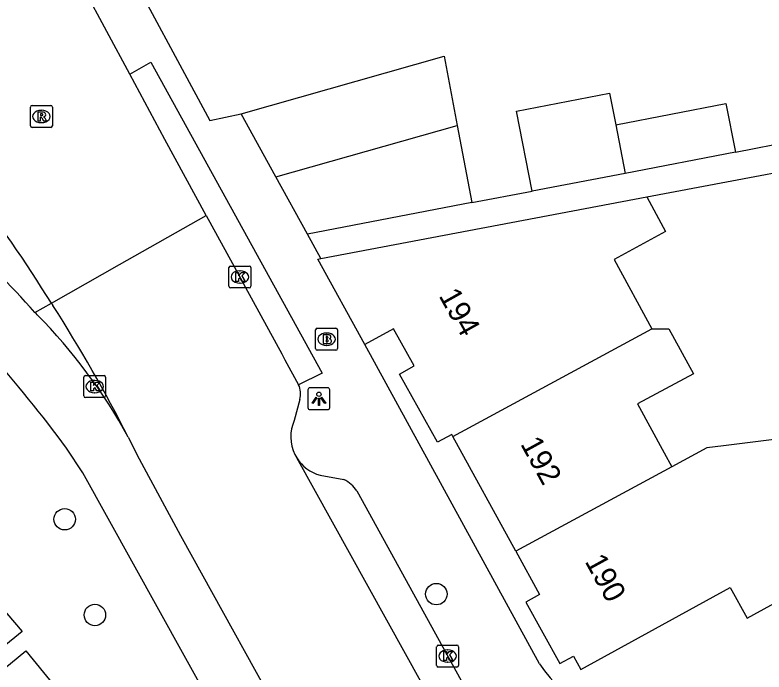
# Model space of a CAD drawing. Extents: x 159053 to 160041, y 380450 to 381422.
# Drawn here: x 159235.06 to 159269.24, y 381203.53 to 381233.5 of the extents above; entities that cross this region are included whole.
import ezdxf

# ---------------------------------------------------------------- set-up
doc = ezdxf.new("R2010")
doc.units = 0
for name, color, linetype in [('IMGEO_Boom', 7, 'Continuous'), ('IMGEO_Brandkraan', 7, 'Continuous'), ('IMGEO_Fietspad_gesloten', 7, 'Continuous'), ('IMGEO_Kolk', 7, 'Continuous'), ('IMGEO_Lage_trafo', 7, 'Continuous'), ('IMGEO_Lichtpunt', 7, 'Continuous'), ('IMGEO_Muur', 7, 'Continuous'), ('IMGEO_Pand', 7, 'Continuous'), ('IMGEO_Pand_nummerreeks', 7, 'Continuous'), ('IMGEO_Parkeervlak_open', 7, 'Continuous'), ('IMGEO_Rijbaan_lokaal_gesloten', 7, 'Continuous'), ('IMGEO_Rioolput', 7, 'Continuous'), ('IMGEO_Voetpad_open', 7, 'Continuous')]:
    doc.layers.add(name, color=color, linetype=linetype)

msp = doc.modelspace()

# ---------------------------------------------------------------- linework, layer by layer
at = {"layer": 'IMGEO_Boom'}
for centre in [(159237.327, 381210.495), (159254.284, 381207.078), (159238.704, 381206.128)]:
    msp.add_circle(centre, 0.489, dxfattribs=at)
at = {"layer": 'IMGEO_Brandkraan'}
for p, q in [((159248.777, 381218.282), (159248.777, 381219.134)), ((159248.852, 381219.208), (159249.704, 381219.208)), ((159249.265, 381218.988), (159249.29, 381218.988)), ((159249.778, 381219.134), (159249.778, 381218.282)), ((159249.288, 381218.428), (159249.263, 381218.428)), ((159249.704, 381218.208), (159248.852, 381218.208))]:
    msp.add_line(p, q, dxfattribs=at)
for points in [[(159248.777, 381218.282), (159248.777, 381219.134)], [(159248.852, 381219.208), (159249.704, 381219.208)], [(159249.778, 381219.134), (159249.778, 381218.282)], [(159249.125, 381218.908), (159249.125, 381218.508), (159249.338, 381218.508)], [(159249.356, 381218.908), (159249.125, 381218.908)], [(159249.304, 381218.827), (159249.25, 381218.827), (159249.25, 381218.751)], [(159249.25, 381218.751), (159249.303, 381218.751)], [(159249.312, 381218.675), (159249.25, 381218.675), (159249.25, 381218.594)], [(159249.25, 381218.594), (159249.312, 381218.594)], [(159249.704, 381218.208), (159248.852, 381218.208)]]:
    msp.add_lwpolyline(points, dxfattribs=at)
for centre, radius, start, end in [((159248.854, 381219.132), 0.0765, 91.552, 178.448), ((159248.854, 381219.132), 0.0765, 91.552, 178.448), ((159249.702, 381219.132), 0.0765, 1.552, 88.448), ((159249.702, 381219.132), 0.0765, 1.552, 88.448), ((159249.305, 381218.789), 0.0379, 267.8285, 90.9355), ((159249.313, 381218.634), 0.0404, 269.8759, 90.5077), ((159249.36, 381218.763), 0.145, 59.4692, 91.5367), ((159249.385, 381218.81), 0.0922, 285.5137, 58.1501), ((159249.39, 381218.618), 0.105, 301.3115, 78.989), ((159248.854, 381218.284), 0.0765, 181.552, 268.448), ((159248.854, 381218.284), 0.0765, 181.552, 268.448), ((159249.344, 381218.759), 0.251, 268.6676, 293.5347), ((159249.702, 381218.284), 0.0765, 271.552, 358.448), ((159249.702, 381218.284), 0.0765, 271.552, 358.448)]:
    msp.add_arc(centre, radius, start, end, dxfattribs=at)
for centre, major_axis, ratio, start_param, end_param in [((159249.264, 381218.708), (-0.387, 0.002), 0.722429, 4.712389, 7.853982), ((159249.289, 381218.708), (-0.39, 0.002), 0.717154, 1.570796, 4.712389)]:
    msp.add_ellipse(centre, major_axis=major_axis, ratio=ratio, start_param=start_param, end_param=end_param, dxfattribs=at)
at = {"layer": 'IMGEO_Fietspad_gesloten'}
for points in [[(159235.971, 381219.934), (159236.718, 381220.356)], [(159236.071, 381219.823), (159236.021, 381219.878), (159235.971, 381219.934)]]:
    msp.add_lwpolyline(points, dxfattribs=at)
for centre, radius, start, end in [((159194.705, 381182.561), 55.674, 42.1662, 52.6419), ((159218.247, 381202.22), 25.051, 28.6786, 44.6428)]:
    msp.add_arc(centre, radius, start, end, dxfattribs=at)
at = {"layer": 'IMGEO_Kolk'}
for p, q in [((159244.895, 381222.047), (159245.747, 381222.047)), ((159244.82, 381221.121), (159244.82, 381221.973)), ((159245.308, 381221.827), (159245.333, 381221.827)), ((159245.821, 381221.973), (159245.821, 381221.121)), ((159245.747, 381221.047), (159244.895, 381221.047)), ((159245.331, 381221.267), (159245.306, 381221.267)), ((159238.194, 381216.121), (159238.194, 381216.973)), ((159238.269, 381217.047), (159239.121, 381217.047)), ((159239.195, 381216.973), (159239.195, 381216.121)), ((159238.682, 381216.827), (159238.707, 381216.827)), ((159238.705, 381216.267), (159238.68, 381216.267)), ((159239.121, 381216.047), (159238.269, 381216.047)), ((159254.299, 381203.828), (159254.299, 381204.68)), ((159254.374, 381204.754), (159255.226, 381204.754)), ((159255.3, 381204.68), (159255.3, 381203.828)), ((159254.787, 381204.534), (159254.812, 381204.534)), ((159254.81, 381203.974), (159254.785, 381203.974)), ((159255.226, 381203.754), (159254.374, 381203.754))]:
    msp.add_line(p, q, dxfattribs=at)
for points in [[(159244.895, 381222.047), (159245.747, 381222.047)], [(159244.82, 381221.121), (159244.82, 381221.973)], [(159245.141, 381221.747), (159245.264, 381221.747), (159245.264, 381221.596), (159245.394, 381221.747), (159245.558, 381221.747), (159245.412, 381221.596), (159245.565, 381221.347), (159245.413, 381221.347), (159245.328, 381221.511), (159245.264, 381221.444), (159245.264, 381221.347), (159245.141, 381221.347), (159245.141, 381221.747)], [(159245.821, 381221.973), (159245.821, 381221.121)], [(159245.747, 381221.047), (159244.895, 381221.047)], [(159238.194, 381216.121), (159238.194, 381216.973)], [(159238.269, 381217.047), (159239.121, 381217.047)], [(159239.195, 381216.973), (159239.195, 381216.121)], [(159238.515, 381216.747), (159238.638, 381216.747), (159238.638, 381216.596), (159238.768, 381216.747), (159238.932, 381216.747), (159238.786, 381216.596), (159238.939, 381216.347), (159238.787, 381216.347), (159238.702, 381216.511), (159238.638, 381216.444), (159238.638, 381216.347), (159238.515, 381216.347), (159238.515, 381216.747)], [(159239.121, 381216.047), (159238.269, 381216.047)], [(159254.299, 381203.828), (159254.299, 381204.68)], [(159254.374, 381204.754), (159255.226, 381204.754)], [(159255.3, 381204.68), (159255.3, 381203.828)], [(159254.62, 381204.454), (159254.743, 381204.454), (159254.743, 381204.303), (159254.873, 381204.454), (159255.037, 381204.454), (159254.891, 381204.303), (159255.044, 381204.054), (159254.892, 381204.054), (159254.807, 381204.218), (159254.743, 381204.151), (159254.743, 381204.054), (159254.62, 381204.054), (159254.62, 381204.454)], [(159255.226, 381203.754), (159254.374, 381203.754)]]:
    msp.add_lwpolyline(points, dxfattribs=at)
for centre, start, end in [((159244.897, 381221.971), 91.552, 178.448), ((159244.897, 381221.971), 91.552, 178.448), ((159245.745, 381221.971), 1.552, 88.448), ((159245.745, 381221.971), 1.552, 88.448), ((159244.897, 381221.123), 181.552, 268.448), ((159244.897, 381221.123), 181.552, 268.448), ((159245.745, 381221.123), 271.552, 358.448), ((159245.745, 381221.123), 271.552, 358.448), ((159238.271, 381216.971), 91.552, 178.448), ((159238.271, 381216.971), 91.552, 178.448), ((159239.119, 381216.971), 1.552, 88.448), ((159239.119, 381216.971), 1.552, 88.448), ((159238.271, 381216.123), 181.552, 268.448), ((159238.271, 381216.123), 181.552, 268.448), ((159239.119, 381216.123), 271.552, 358.448), ((159239.119, 381216.123), 271.552, 358.448), ((159254.376, 381204.678), 91.552, 178.448), ((159254.376, 381204.678), 91.552, 178.448), ((159255.224, 381204.678), 1.552, 88.448), ((159255.224, 381204.678), 1.552, 88.448), ((159254.376, 381203.83), 181.552, 268.448), ((159254.376, 381203.83), 181.552, 268.448), ((159255.224, 381203.83), 271.552, 358.448), ((159255.224, 381203.83), 271.552, 358.448)]:
    msp.add_arc(centre, 0.0765, start, end, dxfattribs=at)
for centre, major_axis, ratio, start_param, end_param in [((159245.307, 381221.547), (-0.387, 0.002), 0.722429, 4.712389, 7.853982), ((159245.332, 381221.547), (-0.39, 0.002), 0.717154, 1.570796, 4.712389), ((159238.681, 381216.547), (-0.387, 0.002), 0.722429, 4.712389, 7.853982), ((159238.706, 381216.547), (-0.39, 0.002), 0.717154, 1.570796, 4.712389), ((159254.786, 381204.254), (-0.387, 0.002), 0.722429, 4.712389, 7.853982), ((159254.811, 381204.254), (-0.39, 0.002), 0.717154, 1.570796, 4.712389)]:
    msp.add_ellipse(centre, major_axis=major_axis, ratio=ratio, start_param=start_param, end_param=end_param, dxfattribs=at)
at = {"layer": 'IMGEO_Lage_trafo'}
msp.add_lwpolyline([(159234.224, 381203.411), (159235.554, 381204.496), (159236.832, 381202.93), (159235.531, 381201.869)], dxfattribs=at)
at = {"layer": 'IMGEO_Lichtpunt'}
for p, q in [((159248.426, 381216.396), (159248.426, 381215.589)), ((159248.426, 381216.396), (159248.426, 381215.589)), ((159249.328, 381216.491), (159248.52, 381216.491)), ((159249.328, 381216.491), (159248.52, 381216.491)), ((159249.422, 381215.589), (159249.422, 381216.396)), ((159249.422, 381215.589), (159249.422, 381216.396)), ((159248.52, 381215.495), (159249.328, 381215.495)), ((159248.52, 381215.495), (159249.328, 381215.495))]:
    msp.add_line(p, q, dxfattribs=at)
for points in [[(159248.8, 381216.06), (159248.839, 381216.032), (159248.651, 381215.77), (159248.613, 381215.797), (159248.8, 381216.06)], [(159248.902, 381216.012), (159248.949, 381216.012), (159248.949, 381215.69), (159248.902, 381215.69), (159248.902, 381216.012)], [(159249.012, 381216.032), (159249.05, 381216.059), (159249.237, 381215.797), (159249.198, 381215.769), (159249.012, 381216.032)]]:
    msp.add_lwpolyline(points, dxfattribs=at)
msp.add_circle((159248.925, 381216.194), 0.0994, dxfattribs=at)
for centre, start, end in [((159248.52, 381216.396), 90, 180), ((159248.52, 381216.396), 90, 180), ((159249.328, 381216.396), 0, 90), ((159249.328, 381216.396), 0, 90), ((159248.52, 381215.589), 180, 270), ((159248.52, 381215.589), 180, 270), ((159249.328, 381215.589), 270, 0), ((159249.328, 381215.589), 270, 360)]:
    msp.add_arc(centre, 0.0946, start, end, dxfattribs=at)
at = {"layer": 'IMGEO_Muur'}
msp.add_lwpolyline([(159237.275, 381243.932), (159239.731, 381236.517), (159243.948, 381228.686), (159245.372, 381228.997)], dxfattribs=at)
at = {"layer": 'IMGEO_Pand'}
for points in [[(159245.372, 381228.997), (159254.638, 381231.622), (159255.241, 381228.458)], [(159258.651, 381225.462), (159257.941, 381229.115), (159262.185, 381229.94), (159262.468, 381228.486)], [(159262.468, 381228.486), (159267.497, 381229.462), (159267.929, 381227.242)], [(159246.963, 381226.113), (159245.372, 381228.997)], [(159246.963, 381226.113), (159255.241, 381228.458)], [(159255.241, 381228.458), (159255.91, 381224.943)], [(159262.468, 381228.486), (159262.901, 381226.266)], [(159267.929, 381227.242), (159262.901, 381226.266)], [(159248.408, 381223.494), (159246.963, 381226.113)], [(159262.901, 381226.266), (159258.651, 381225.462)], [(159249.008, 381222.383), (159263.884, 381225.197)], [(159263.884, 381225.197), (159264.74, 381223.618), (159262.398, 381222.348), (159264.113, 381219.183)], [(159255.91, 381224.943), (159248.408, 381223.494)], [(159251.017, 381218.464), (159248.878, 381222.358), (159249.008, 381222.383)], [(159255.043, 381214.266), (159254.987, 381214.368), (159254.331, 381214.006), (159252.61, 381217.116), (159253.279, 381217.494), (159252.331, 381219.186), (159251.017, 381218.464)], [(159255.043, 381214.266), (159264.113, 381219.183)], [(159264.113, 381219.183), (159264.9, 381219.183), (159266.012, 381217.131), (159263.469, 381215.753), (159264.675, 381213.528), (159265.023, 381212.885)], [(159257.915, 381209.032), (159255.043, 381214.266)], [(159270.667, 381214.25), (159267.381, 381213.843), (159266.628, 381213.755), (159265.023, 381212.885)], [(159265.023, 381212.885), (159257.915, 381209.032)], [(159257.915, 381209.032), (159258.997, 381207.059), (159258.375, 381206.718), (159259.914, 381203.912), (159260.536, 381204.254), (159260.873, 381203.64), (159267.694, 381207.382), (159268.464, 381205.98), (159271.405, 381207.593), (159273.301, 381206.946), (159273.595, 381207.806), (159277.18, 381207.569)]]:
    msp.add_lwpolyline(points, dxfattribs=at)
at = {"layer": 'IMGEO_Parkeervlak_open'}
msp.add_lwpolyline([(159216.723, 381219.836), (159220.387, 381222.952), (159235.387, 381205.379), (159233.711, 381204.017)], dxfattribs=at)
at = {"layer": 'IMGEO_Rijbaan_lokaal_gesloten'}
for points in [[(159240.3, 381230.796), (159238.2, 381234.713), (159237.21, 381237.061), (159236.582, 381239.242), (159235.793, 381242.082), (159235.5, 381242.849)], [(159243.787, 381224.352), (159241.894, 381227.823), (159240.3, 381230.796)], [(159236.718, 381220.356), (159239.829, 381222.114), (159243.787, 381224.352)], [(159243.787, 381224.352), (159245.235, 381221.698), (159245.581, 381221.065), (159247.23, 381218.043), (159247.378, 381217.772), (159248, 381216.631)], [(159236.718, 381220.356), (159236.754, 381220.298), (159236.79, 381220.24)], [(159248.054, 381215.964), (159247.803, 381215)], [(159240.225, 381214.242), (159240.73, 381213.257), (159242.603, 381209.758), (159247.946, 381200.118), (159248.659, 381198.85)], [(159247.834, 381213.452), (159247.92, 381213.298)], [(159255.28, 381200.018), (159247.92, 381213.298)]]:
    msp.add_lwpolyline(points, dxfattribs=at)
for centre, radius, start, end in [((159178.831, 381184.36), 68.166, 31.87413, 43.03593), ((159178.901, 381183.105), 68.776, 26.91906, 32.67969), ((159247.145, 381216.226), 0.946, 343.9096, 25.3475), ((159249.458, 381214.259), 1.814, 155.8794, 206.4151)]:
    msp.add_arc(centre, radius, start, end, dxfattribs=at)
at = {"layer": 'IMGEO_Rioolput'}
for p, q in [((159235.763, 381228.444), (159235.763, 381229.296)), ((159235.838, 381229.37), (159236.69, 381229.37)), ((159236.764, 381229.296), (159236.764, 381228.444)), ((159236.251, 381229.15), (159236.276, 381229.15)), ((159236.274, 381228.59), (159236.249, 381228.59)), ((159236.69, 381228.37), (159235.838, 381228.37))]:
    msp.add_line(p, q, dxfattribs=at)
for points in [[(159235.763, 381228.444), (159235.763, 381229.296)], [(159235.838, 381229.37), (159236.69, 381229.37)], [(159236.764, 381229.296), (159236.764, 381228.444)], [(159236.352, 381229.068), (159236.1, 381229.07), (159236.1, 381228.67)], [(159236.1, 381228.67), (159236.224, 381228.67), (159236.224, 381228.832), (159236.235, 381228.832)], [(159236.278, 381228.989), (159236.224, 381228.989), (159236.224, 381228.908)], [(159236.224, 381228.908), (159236.276, 381228.908)], [(159236.282, 381228.803), (159236.353, 381228.67), (159236.493, 381228.67), (159236.428, 381228.796)], [(159236.69, 381228.37), (159235.838, 381228.37)]]:
    msp.add_lwpolyline(points, dxfattribs=at)
for centre, radius, start, end in [((159235.84, 381229.294), 0.0765, 91.552, 178.448), ((159235.84, 381229.294), 0.0765, 91.552, 178.448), ((159236.688, 381229.294), 0.0765, 1.552, 88.448), ((159236.688, 381229.294), 0.0765, 1.552, 88.448), ((159236.234, 381228.779), 0.0533, 26.0293, 88.6989), ((159236.26, 381229.097), 0.19, 274.7715, 282.9687), ((159236.284, 381228.893), 0.0964, 77.0061, 93.1865), ((159236.298, 381228.95), 0.0378, 276.6634, 79.6772), ((159236.351, 381228.958), 0.109, 350.3612, 89.416), ((159236.349, 381228.958), 0.112, 277.5842, 350.9817), ((159236.333, 381228.743), 0.108, 29.5134, 73.7905), ((159235.84, 381228.446), 0.0765, 181.552, 268.448), ((159235.84, 381228.446), 0.0765, 181.552, 268.448), ((159236.688, 381228.446), 0.0765, 271.552, 358.448), ((159236.688, 381228.446), 0.0765, 271.552, 358.448)]:
    msp.add_arc(centre, radius, start, end, dxfattribs=at)
for centre, major_axis, ratio, start_param, end_param in [((159236.25, 381228.87), (-0.387, 0.002), 0.722429, 4.712389, 7.853982), ((159236.275, 381228.87), (-0.39, 0.002), 0.717154, 1.570796, 4.712389)]:
    msp.add_ellipse(centre, major_axis=major_axis, ratio=ratio, start_param=start_param, end_param=end_param, dxfattribs=at)
at = {"layer": 'IMGEO_Voetpad_open'}
for points in [[(159237.275, 381243.932), (159239.731, 381236.517), (159243.948, 381228.686), (159245.372, 381228.997)], [(159240.3, 381230.796), (159241.254, 381231.353), (159249.08, 381217.163), (159248, 381216.631)], [(159267.929, 381227.242), (159270.56, 381227.754)], [(159263.884, 381225.197), (159275.037, 381227.303)], [(159255.91, 381224.943), (159258.651, 381225.462)], [(159249.008, 381222.383), (159248.408, 381223.494)], [(159258.985, 381203.899), (159251.017, 381218.464)], [(159247.477, 381195.81), (159238.149, 381212.61), (159237.404, 381213.74)], [(159248.983, 381212.499), (159250.067, 381212.301)], [(159250.653, 381211.784), (159255.411, 381203.141)]]:
    msp.add_lwpolyline(points, dxfattribs=at)
for centre, radius, start, end in [((159189.448, 381178.555), 59.479, 36.26753, 47.1655), ((159249.47, 381214.254), 1.821, 211.6588, 254.4807), ((159249.459, 381211.021), 1.417, 32.573, 64.5862), ((159264.15, 381207.353), 6.213, 213.7713, 271.9017)]:
    msp.add_arc(centre, radius, start, end, dxfattribs=at)

# ---------------------------------------------------------------- texts
at = {"layer": 'IMGEO_Pand_nummerreeks'}
for s, rotation, p in [('194', 299.2612, (159254.374, 381220.694)), ('192', 298.7508, (159258.1, 381213.932)), ('190', 298.7508, (159261.039, 381208.575))]:
    msp.add_text(s, height=1, rotation=rotation, dxfattribs=at).set_placement(p)

doc.saveas('drawing.dxf')
